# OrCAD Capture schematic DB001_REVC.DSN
size B
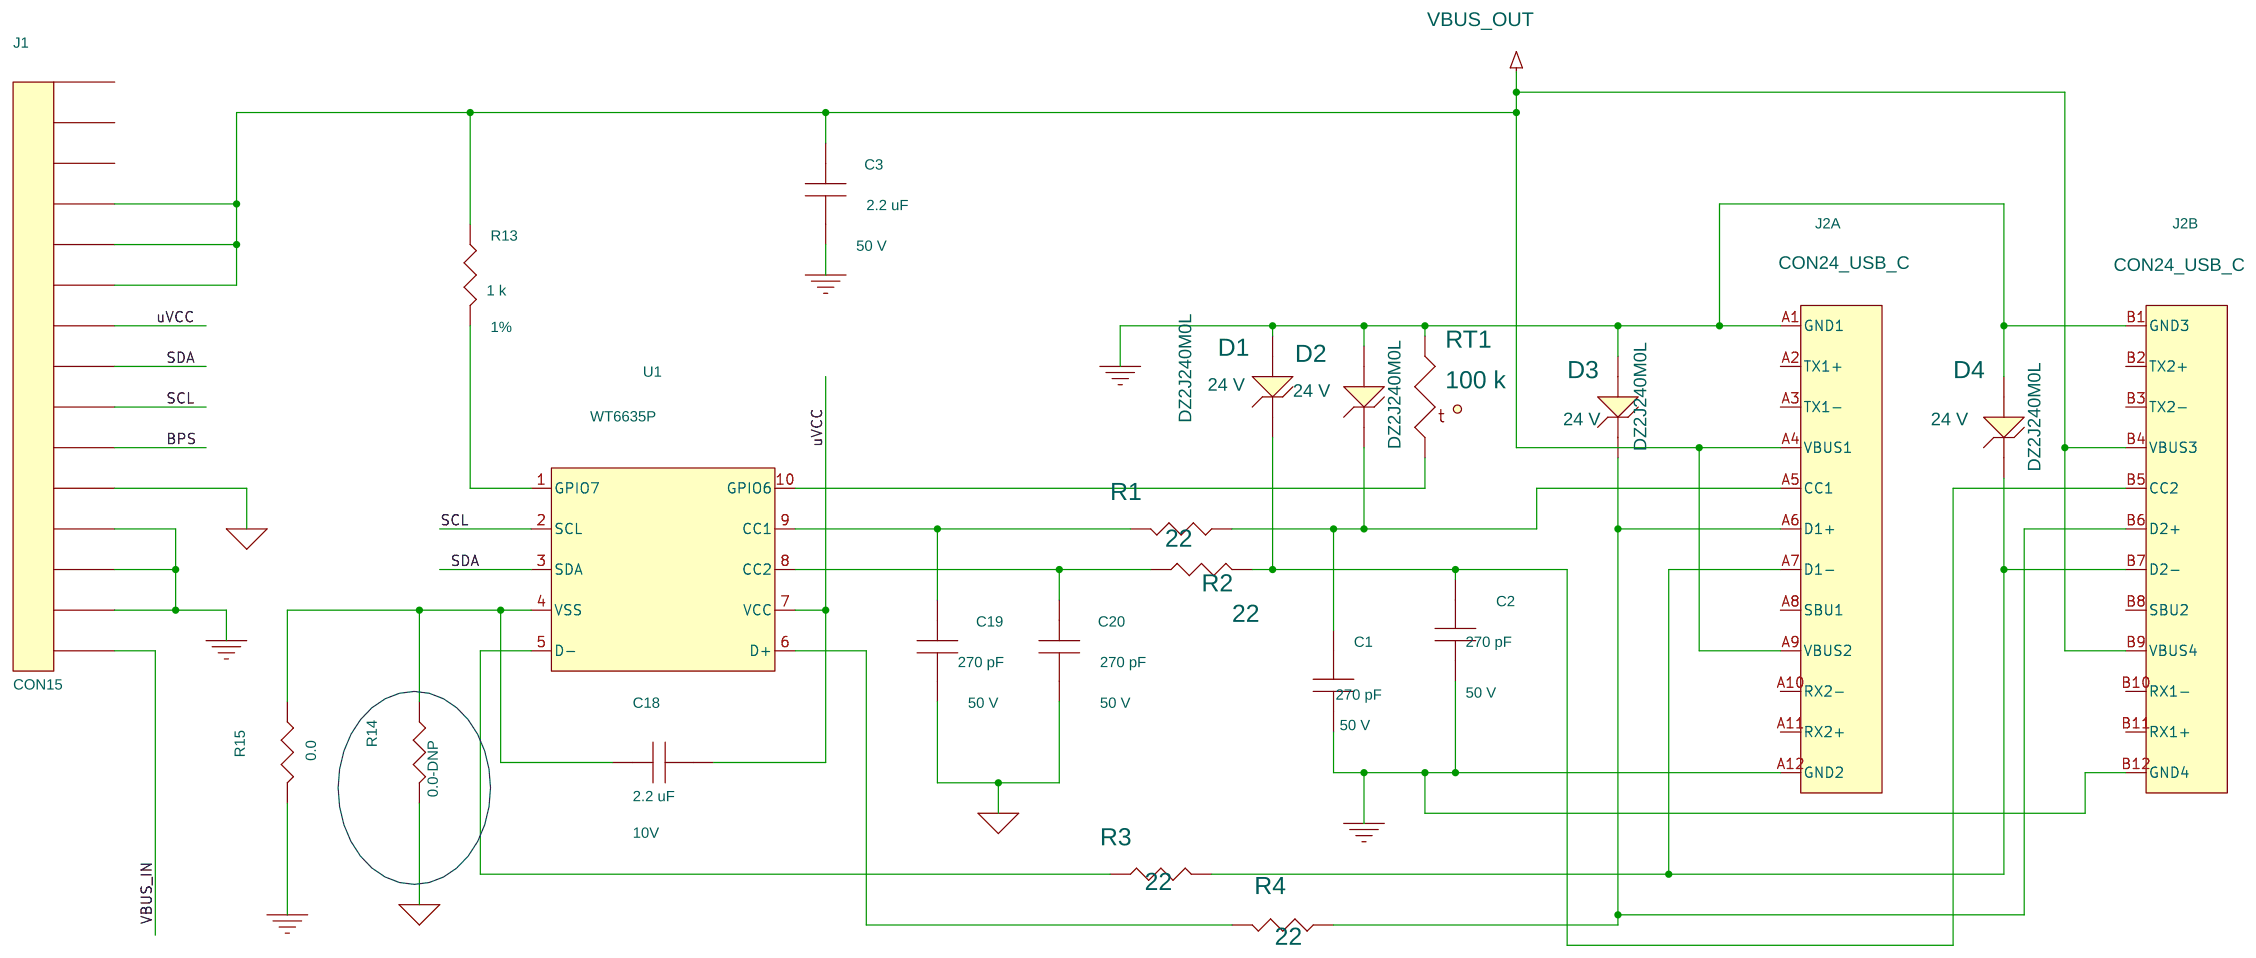
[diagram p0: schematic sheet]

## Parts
C1  270 pF  [pismc0603]
C2  270 pF  [pismc0603]
C3  2.2 uF  [pismc1206]
C18  2.2 uF  [pismc0603]
C19  270 pF  [pismc0603]
C20  270 pF  [pismc0603]
D1  DZ2J240M0L  [pi_sm_d_ssmini2p]
D2  DZ2J240M0L  [pi_sm_d_ssmini2p]
D3  DZ2J240M0L  [pi_sm_d_ssmini2p]
D4  DZ2J240M0L  [pi_sm_d_ssmini2p]
J1  CON15  [pi_unshroud_2mm_15pra]
J2  CON24_USB_C  [pi_conn_USBC_Wurth]  (sections A,B)
R1  22  [pismr0603]
R2  22  [pismr0603]
R3  22  [pismr0603]
R4  22  [pismr0603]
R13  1 k  [pismr0603]
R14  0.0-DNP  [pismr0603]
R15  0.0  [pismr0603]
RT1  100 k  [pismr0603]
U1  WT6635P  [pismsop10]

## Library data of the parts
C1 C2 C19 C20 = CAP_NP: Disp_Voltage: 50 V; Part Number: 20-09122-00; Voltage: 50 V
C3 = CAP_NP: Disp_Voltage: 50 V; Part Number: 20-00723-00; Voltage: 50 V
C18 = CAP_NP: Disp_Voltage: 10V; Part Number: 20-00983-00; Voltage: 10 V
D1-D4 = DIODE_ZENER: Disp_Voltage: 24 V; Part Number: 15-01042-00
J1 = CON15: Part Number: 35-00429-00
J2 = CON24_USB: Part Number: 35-00414-00
R1-R4 = R: COMPGROUP: 1; Part Number: 05-01648-00
R13 = R: Disp_Tol: 1%; Part Number: 05-01078-00
R14 R15 = R: Part Number: 05-03158-00
RT1 = THERMISTOR: Part Number: 90-00063-00
U1 = WT6635P-10: Part Number: 45-00487-00

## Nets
GND: C1.1 C2.1 C3.2 D1.2 D2.2 D3.2 D4.2 J1.2 J1.3 J1.4 J2.A1(GND1) J2.A12(GND2) J2.B1(GND3) J2.B12(GND4) R15.2 RT1.1
GND_SIGNAL: C19.2 C20.2 J1.5 R14.2
VBUS_IN: J1.1
VBUS_OUT: C3.1 J1.10 J1.11 J1.12 J2.A4(VBUS1) J2.A9(VBUS2) J2.B4(VBUS3) J2.B9(VBUS4) R13.2
BPS: J1.6
SCL: J1.7 U1.2(SCL)
SDA: J1.8 U1.3(SDA)
uVCC: C18.2 J1.9 U1.7(VCC)
N12116712: C2.2 D1.1 J2.B5(CC2) R2.1
N12116716: C1.2 D2.1 J2.A5(CC1) R1.2
N12116772: RT1.2 U1.10(GPIO6)
N12116776: D3.1 J2.A6(D1+) J2.B6(D2+) R4.2
N12116788: R13.1 U1.1(GPIO7)
N12116812: D4.1 J2.A7(D1-) J2.B7(D2-) R3.1
N12116850: C19.1 R1.1 U1.9(CC1)
N12116916: C20.1 R2.2 U1.8(CC2)
N12116972: C18.1 R14.1 R15.1 U1.4(VSS)
N12121431: R3.2 U1.5(D-)
N12121586: R4.1 U1.6(D+)

Not connected (* = marked no-connect by the designer): J1 13 14 15; J2 A2(TX1+) A3(TX1-) A8(SBU1) A10(RX2-) A11(RX2+) B2(TX2+) B3(TX2-) B8(SBU2) B10(RX1-) B11(RX1+)
